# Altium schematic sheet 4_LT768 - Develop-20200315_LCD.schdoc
size 805 x 261 mm
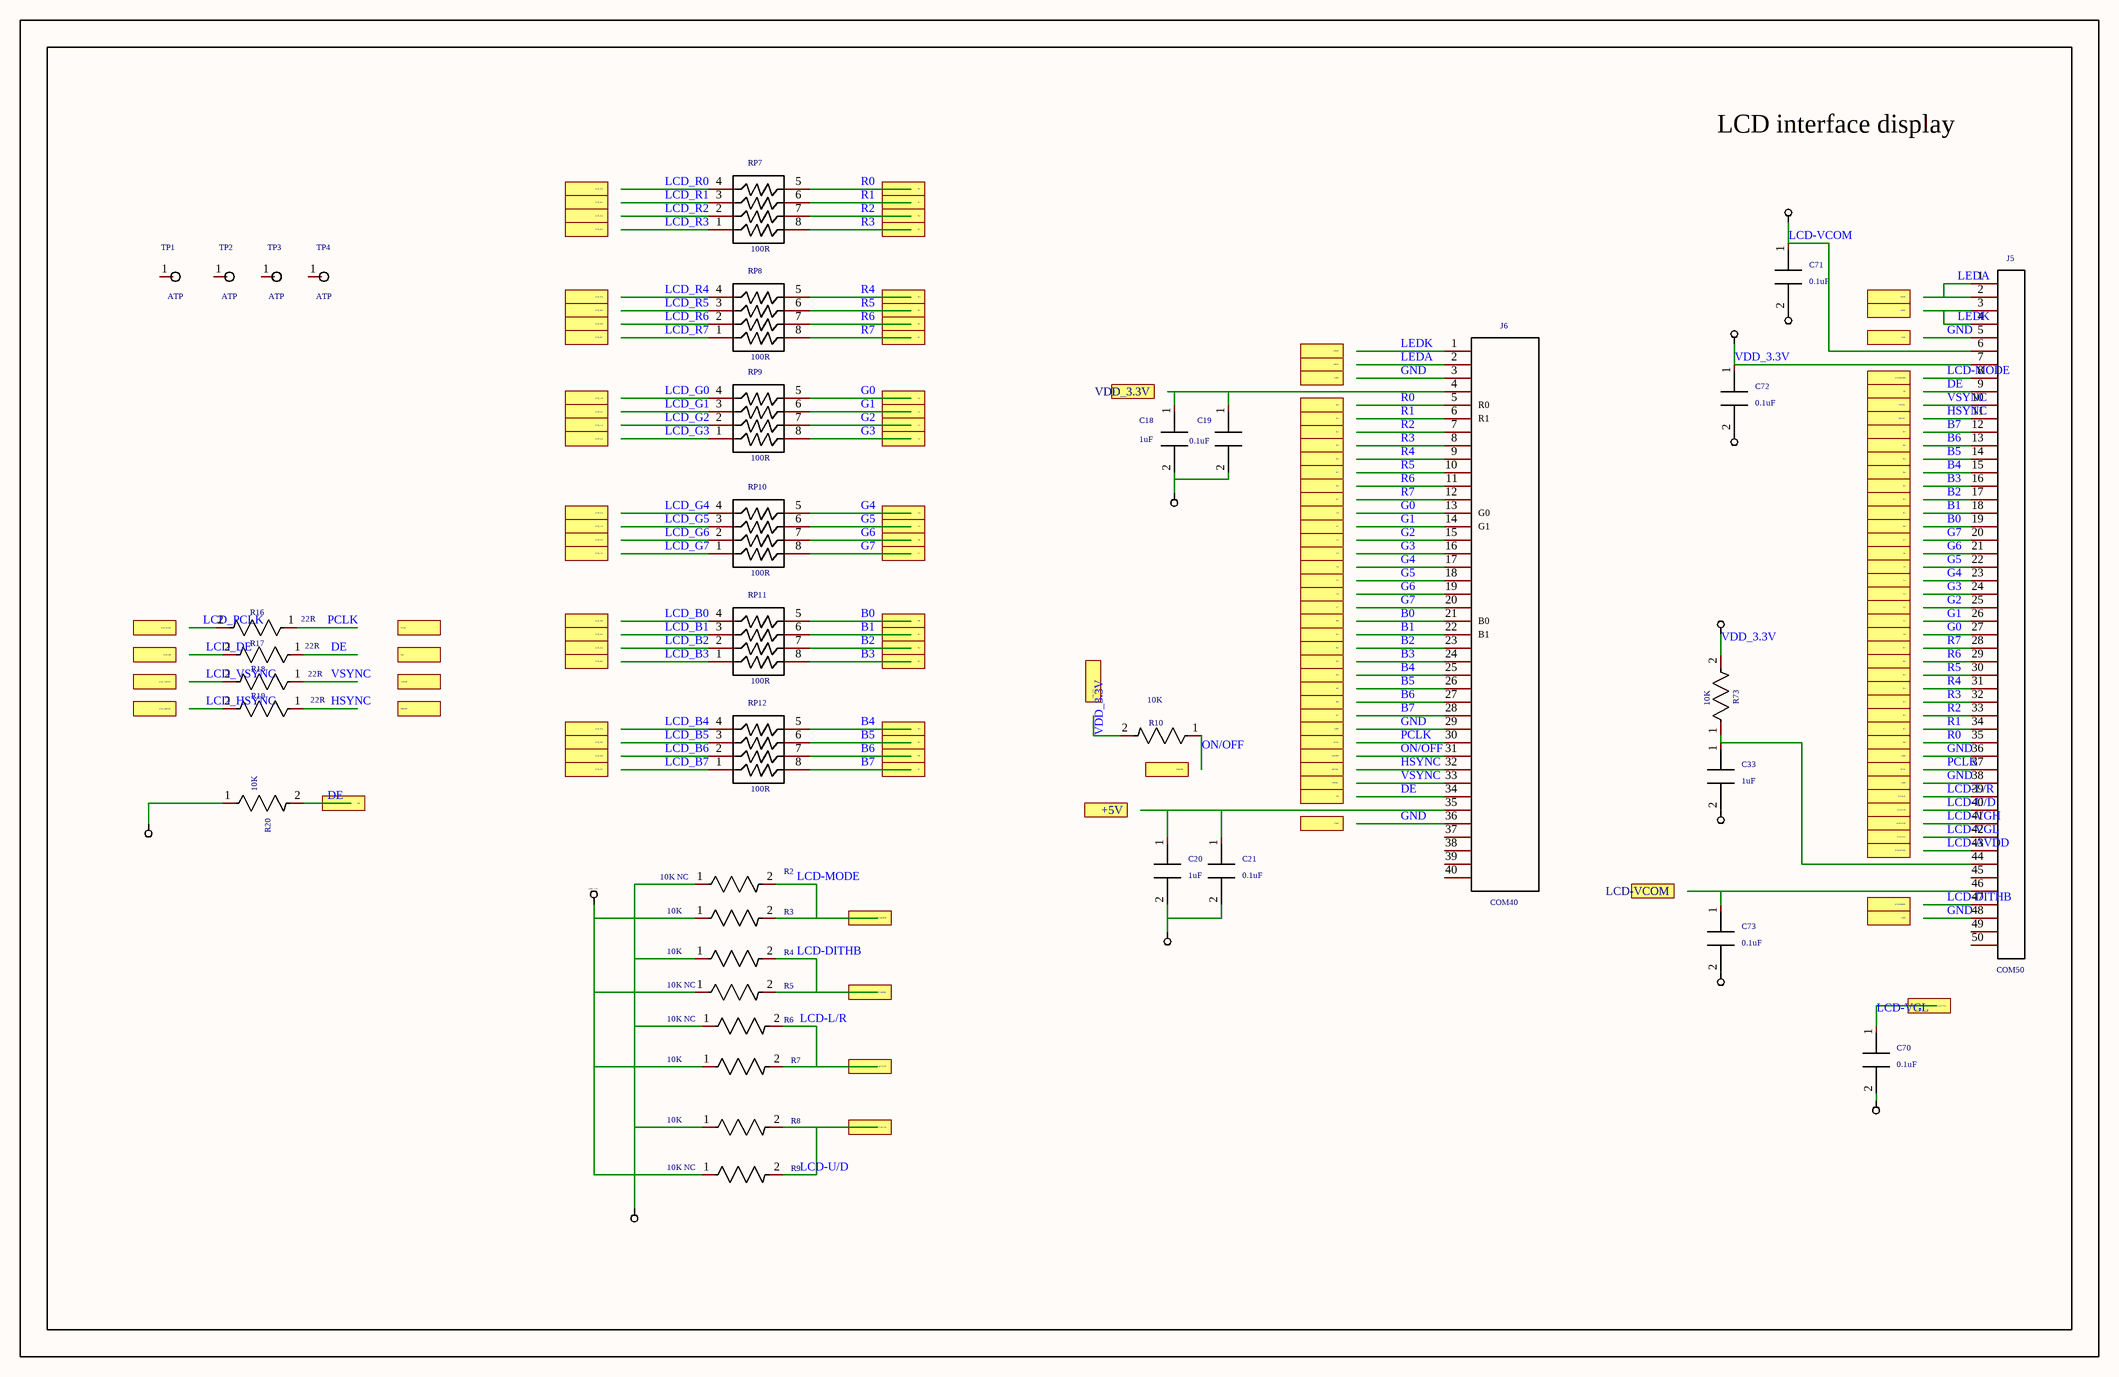
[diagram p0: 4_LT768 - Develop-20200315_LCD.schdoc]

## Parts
C18  1uF
C19  0.1uF
C20  1uF
C21  0.1uF
C33  1uF
C70  0.1uF
C71  0.1uF
C72  0.1uF
C73  0.1uF
J5  COM50
J6  COM40
R2  10K NC
R3  10K
R4  10K
R5  10K NC
R6  10K NC
R7  10K
R8  10K
R9  10K NC
R10  10K
R16  22R
R17  22R
R18  22R
R19  22R
R20  10K
R73  10K
RP7  100R
RP8  100R
RP9  100R
RP10  100R
RP11  100R
RP12  100R
TP1  ATP
TP2  ATP
TP3  ATP
TP4  ATP

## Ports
+5V (in), B0 (in), B1 (in), B2 (in), B3 (in), B4 (in), B5 (in), B6 (in), B7 (in), DE (in), DE (out), G0 (in), G1 (in), G2 (in), G3 (in), G4 (in), G5 (in), G6 (in), G7 (in), GND (in), HSYNC (in), HSYNC (out), LCD-AVDD (in), LCD-DITHB (in), LCD-L/R (in), LCD-MODE (in), LCD-U/D (in), LCD-VCOM (in), LCD-VGH (in), LCD-VGL (in), LCD_B0 (in), LCD_B1 (in), LCD_B2 (in), LCD_B3 (in), LCD_B4 (in), LCD_B5 (in), LCD_B6 (in), LCD_B7 (in), LCD_DE (in), LCD_G0 (in), LCD_G1 (in), LCD_G2 (in), LCD_G3 (in), LCD_G4 (in), LCD_G5 (in), LCD_G6 (in), LCD_G7 (in), LCD_HSYNC (in), LCD_PCLK (in), LCD_R0 (in), LCD_R1 (in), LCD_R2 (in), LCD_R3 (in), LCD_R4 (in), LCD_R5 (in), LCD_R6 (in), LCD_R7 (in), LCD_VSYNC (in), LEDA (in), LEDK (in), ON/OFF (in), PCLK (in), PCLK (out), R0 (in), R1 (in), R2 (in), R3 (in), R4 (in), R5 (in), R6 (in), R7 (in), VDD_3.3V (in), VSYNC (in), VSYNC (out)

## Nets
GND: C18.2 C19.2 C20.2 C21.2 C33.2 C70.2 C71.2 C72.2 C73.2 J5.5 J5.36 J5.38 J5.48 J6.3 J6.29 J6.36 R2.1 R4.1 R6.1 R8.1 R20.1
LCD-VCOM: C71.1 J5.6
VDD_3.3V: C72.1 J5.7 R3.1 R5.1 R7.1 R9.1 R10.2 R73.2
B0: J5.19 J6.21 RP11.5 ; port B0
B1: J5.18 J6.22 RP11.6 ; port B1
B2: J5.17 J6.23 RP11.7 ; port B2
B3: J5.16 J6.24 RP11.8 ; port B3
B4: J5.15 J6.25 RP12.5 ; port B4
B5: J5.14 J6.26 RP12.6 ; port B5
B6: J5.13 J6.27 RP12.7 ; port B6
B7: J5.12 J6.28 RP12.8 ; port B7
DE: J5.9 J6.34 R17.1 R20.2 ; port DE
G0: J5.27 J6.13 RP9.5 ; port G0
G1: J5.26 J6.14 RP9.6 ; port G1
G2: J5.25 J6.15 RP9.7 ; port G2
G3: J5.24 J6.16 RP9.8 ; port G3
G4: J5.23 J6.17 RP10.5 ; port G4
G5: J5.22 J6.18 RP10.6 ; port G5
G6: J5.21 J6.19 RP10.7 ; port G6
G7: J5.20 J6.20 RP10.8 ; port G7
HSYNC: J5.11 J6.32 R19.1
LCD-AVDD: J5.43
LCD-DITHB: J5.47 R4.2 R5.2 ; port LCD-DITHB
LCD-L/R: J5.39 R6.2 R7.2 ; port LCD-L/R
LCD-MODE: J5.8 R2.2 R3.2 ; port LCD-MODE
LCD-U/D: J5.40 R8.2 R9.2 ; port LCD-U/D
LCD-VGH: J5.41
LCD-VGL: C70.1 J5.42 ; port LCD-VGL
LCD_B0: RP11.4
LCD_B1: RP11.3
LCD_B2: RP11.2
LCD_B3: RP11.1
LCD_B4: RP12.4
LCD_B5: RP12.3
LCD_B6: RP12.2
LCD_B7: RP12.1
LCD_DE: R17.2
LCD_G0: RP9.4
LCD_G1: RP9.3
LCD_G2: RP9.2
LCD_G3: RP9.1
LCD_G4: RP10.4
LCD_G5: RP10.3
LCD_G6: RP10.2
LCD_G7: RP10.1
LCD_HSYNC: R19.2
LCD_PCLK: R16.2
LCD_R0: RP7.4
LCD_R1: RP7.3
LCD_R2: RP7.2
LCD_R3: RP7.1
LCD_R4: RP8.4
LCD_R5: RP8.3
LCD_R6: RP8.2
LCD_R7: RP8.1
LCD_VSYNC: R18.2
LEDA: J5.1 J5.2 J6.2
LEDK: J5.3 J5.4 J6.1
ON/OFF: J6.31 R10.1
PCLK: J5.37 J6.30 R16.1
R0: J5.35 J6.5 RP7.5 ; port R0
R1: J5.34 J6.6 RP7.6 ; port R1
R2: J5.33 J6.7 RP7.7 ; port R2
R3: J5.32 J6.8 RP7.8 ; port R3
R4: J5.31 J6.9 RP8.5 ; port R4
R5: J5.30 J6.10 RP8.6 ; port R5
R6: J5.29 J6.11 RP8.7 ; port R6
R7: J5.28 J6.12 RP8.8 ; port R7
VSYNC: J5.10 J6.33 R18.1
NetC18_1: C18.1 C19.1 J6.4
NetC20_1: C20.1 C21.1 J6.35
NetC33_1: C33.1 J5.44 R73.1
NetC73_1: C73.1 J5.46

Not connected (* = marked no-connect by the designer): J5 45 49 50; J6 37 38 39 40; TP1 1; TP2 1; TP3 1; TP4 1

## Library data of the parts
C18-C21 C33 C70-C73 = CAP0603: Capacitor; PART DESC: CERAMIC CAP.0.1UF/50V +/-20% 0603; PART NO: 014104BZ2503; PART NUMBER: 022-109600310-00; Symbol: CAP; Add into BOM: yes; _: 0.0103; PCB DECAL: C0603
J5 = COM50: Connector; Add into BOM: yes; PCB DECAL: FPC50-0.5
J6 = COM40: Connector; Add into BOM: yes; PCB DECAL: FPC40-0.5
R2-R10 R16-R20 R73 = RES: Resistance; Symbol: RESZ-V; Add into BOM: yes; PCB DECAL: R0603
RP7-RP12 = RP4: Resistor Packs; Symbol: RP-4; Add into BOM: yes; PCB DECAL: 8R4R
TP1-TP4 = ATP: Symbol: TP; Add into BOM: no; Convert to PCB: yes; PCB DECAL: AP1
